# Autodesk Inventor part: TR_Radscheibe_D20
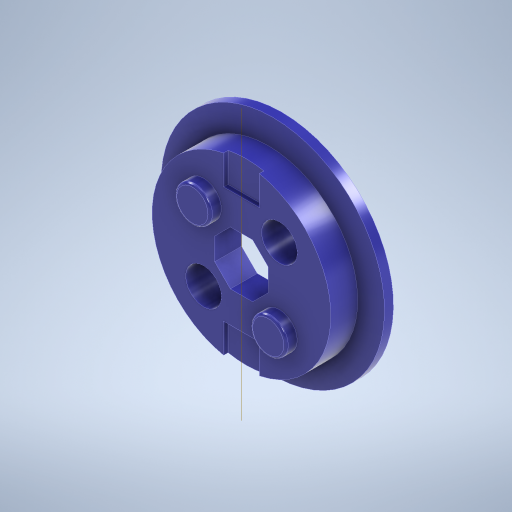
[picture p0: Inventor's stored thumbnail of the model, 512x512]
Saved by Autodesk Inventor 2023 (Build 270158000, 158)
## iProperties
Created: 2023-11
Part Number: TR_Radscheibe_D20
Material: PC/ABS-Kunststoff
Document SubType Name: Modeling
Designer: Administrator
Density: 0.357273 g/cm^3
Appearance: Glatt - Marine
Author: Administrator
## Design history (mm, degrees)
sketch "Skizze1"
  geometry: L1 (0, 0)-(0, -3); L2 (0, -3)-(8.5, -3); L3 (8.5, -3)-(8.5, -4.5); L4 (8.5, -4.5)-(12.5, -4.5); L5 (12.5, -4.5)-(12.5, -3.5); L6 (12.5, -3.5)-(10, -3); L7 (10, -3)-(10, 0); L8 (10, 0)-(0, 0)
  constraints: 16 end point, 5 perpendicular, 1 parallel, 1 vertical
  dimensions: "d0" = 3 distance of L1.start L1.end; "d1" = 4.5 distance from line of L1.start L4; "d2" = 1 distance of L5.end L4.end; "d3" = 1.5 vertical distance of L4.end L6.end; "d4" = 4 distance of L3.end L4.end; "d5" = 10 distance between parallel lines of L1 L7; "d6" = 12.5 horizontal distance of L1.start L5.end
revolve "Umdrehung1" sketch "Skizze1" stored, may be unused: angle "d7" = 90 deg
sketch "Skizze2"
  geometry: L1 (3, -1.243)-(1.243, -3); L2 (1.243, -3)-(-1.243, -3); L3 (-1.243, -3)-(-3, -1.243); L4 (-3, -1.243)-(-3, 1.243); L5 (-3, 1.243)-(-1.243, 3); L6 (-1.243, 3)-(1.243, 3); L7 (1.243, 3)-(3, 1.243); L8 (3, 1.243)-(3, -1.243); 2 further points
  constraints: 16 end point, 1 coincident, 1 horizontal, 17 other
  dimensions: "d8" = 6 distance between parallel lines of L8 L4 (= AchteckUmkreis)
extrude "Extrusion1" cut sketch "Skizze2" extent not by distance; stored distance "d9" = 0; taper "d10" = 0 deg
sketch "Skizze3"
  geometry: L1 (-4.243, 4.243)-(0, 0); L2 (0, -17.5)-(0, 17.5) reference; C1 r 2 at (-4.243, 4.243)
  constraints: 2 end point, 1 centre point
  dimensions: "d11" = 4 diameter of C1; "d12" = 6 distance of L1.end L1.start; "d13" = 45 deg angle of L2 L1
extrude "Extrusion2" cut sketch "Skizze3" extent not by distance; stored distance "d14" = 0; taper "d15" = 0 deg
pattern_circular "Runde Anordnung1" dims angle "d17" = 360 deg
sketch "Skizze4"
  geometry: L1 (0, 0)-(-4.243, 4.243); L2 (0, -17.5)-(0, 17.5) reference; C1 r 2 at (-4.243, 4.243)
  constraints: 2 end point, 1 centre point
  dimensions: "d19" = 4 diameter of C1; "d20" = 6 distance of L1.start L1.end; "d21" = 45 deg angle of L2 L1
extrude "Extrusion3" join sketch "Skizze4" distance "d22" = 1.25; taper "d23" = 0 deg
fillet "Rundung1" dims "d24" = 0.25
pattern_circular "Runde Anordnung2" dims angle "d26" = 360 deg
sketch "Skizze5"
  geometry: L1 (-2, 10)-(2, 10); L2 (2, 10)-(2, 6.5); L3 (2, 6.5)-(-2, 6.5); L4 (-2, 6.5)-(-2, 10); L5 (0, -17.5)-(0, 17.5) reference; 3 further points
  constraints: 8 end point, 2 parallel, 1 horizontal, 1 midpoint, 1 perpendicular, 1 point on line, 1 vertical alignment, 1 other
  dimensions: "d28" = 4 distance of L1.start L1.end; "d29" = 6.5 vertical distance of point (0, 0) L2.end
extrude "Extrusion4" cut sketch "Skizze5" distance "d30" = 0.5; taper "d31" = 0 deg
mirror "Spiegeln1"
node "Volumenkörper1"
other parameters: "Radius" = 2.075 [user parameter], "Fasen" = 0.5 [user parameter], "Dicke" = 0.8 [user parameter], "Breitloch" = 2 [user parameter], "Langloch" = 32 [user parameter], "AchteckUmkreis" = 6 [user parameter; used in 1 equation term], "DAchsAufnahme" = 4.1 [user parameter], "AchsDurchmesser" = 4 [user parameter], "AchsFase" = 0.5 [user parameter]
